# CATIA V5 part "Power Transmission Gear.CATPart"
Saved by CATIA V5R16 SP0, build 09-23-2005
Part number: Housing
Bounding box of the stored display mesh (mm): x -51 to 51, y 0 to 88, z 0 to 134.987
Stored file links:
  C:\V5_education\CATIA Data\ASD\Power Transmission Gear Assembly\Assembly Data\Power Transmission Gear.CATPart
  C:\V5_education\CATIA Data\ASD\Power Transmission Gear Assembly\Power Transmission Gear Assembly.CATProduct
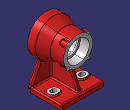
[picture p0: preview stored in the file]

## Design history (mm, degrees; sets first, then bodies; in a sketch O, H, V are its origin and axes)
Set1 "Reference Data"
  Point1 "Center Point": (0, 0, 0)
  Point2 "Hard Point": (0, 0, 91), relative to Point1
  Set2 "Datum Body"
    Plane1: type Offset, RefPlane zx-plane, Offset 88
    Plane2: type Offset, RefPlane zx-plane, Offset 76
    Plane3: type Offset, RefPlane zx-plane, Offset 6
    Plane4: type Offset, RefPlane xy-plane, Offset 4
    Plane5: type Offset, RefPlane yz-plane, Offset 51 {= -Plane6.Offset}
    Plane6: type Offset, RefPlane yz-plane, Offset -51
  Extrude1: Element1 Sketch1, Lim1 201, Lim2 115, Direction zx-plane
  Sketch1 on zx-plane, origin (0, 0, 0), H (-1, 0, 0), V (0, 0, 1)
    point P1 (0, 167.3167)
    line L1 (0, 167.3167) -> (0, 91)
    line L2 (0, 91) -> (-87.8725, 91)
    distance H L2 = 91
    coincidence: P1 V
    vertical: L1 V
    horizontal: L2 H
Body1 (main body)
  Body2 "Revolution Body"
    Sketch2 on yz-plane, origin (0, 0, 0), H (0, 1, 0), V (0, 0, 1)
      reference projected point E1 (0, 91) from Point2
      point P1 (0, 91)
      line L1 (0, 91) -> (0, 135)
      line L2 (0, 135) -> (18, 135)
      point P3 (18, 135)
      line L3 (18, 135) -> (44, 125.5)
      point P4 (44, 125.5)
      line L4 (44, 125.5) -> (76, 125.5)
      line L5 (76, 125.5) -> (76, 91)
      axis line L6 (0, 91) -> (76, 91)
      reference intersected line E2 through (76, 0) direction (0, 1) from Plane2
      distance L1 P4 = 44
      distance L1 P3 = 18
      distance L2 L6 = 44
      distance L6 L4 = 34.5
      vertical: L1 V, L5 V
      horizontal: L2 H, L6 H
      coincidence: L1 E1, P1 E1, L5 E2
    Shaft1: profile Sketch2, axis Sketch2.L6, angle 360
    Fillet1: radius 3, on edge [face of Shaft1 from Sketch2.L2 | face of Shaft1 from Sketch2.L3]; edge [face of Shaft1 from Sketch2.L3 | face of Shaft1 from Sketch2.L4]
    Body3
      Sketch3 on Plane2, origin (0, 76, 91), H (-1, 0, 0), V (0, 0, 1)
        construction circle A1 centre (0, 0) radius 32
        circle A2 centre (22.6274, 22.6274) radius 6
        point P1 (22.6274, 22.6274)
        construction line L1 (22.6274, 22.6274) -> (0, 0)
        radius A1 = 32
        angle H L1 = 45
        radius A2 = 6
        coincidence: P1 A1
      Pad1: profile Sketch3, direction (0, -1, 0), length 16
      Fillet2: radius 3, on end face of Pad1
      CircPattern1: of the body so far, instances 4, angular step 90 {= 360.0*1 deg/CircPattern1.AngularNumber}, axis from face of Shaft1 from Sketch2.L4
    Assemble1: tool Body3
    Fillet3: radius 3, on edge [face of Shaft1 from Sketch2.L4 | face of CircPattern1] (x3); edge [face of Pad1 from Sketch3.A2 | face of Shaft1 from Sketch2.L4]
  Assemble2: tool Body2
  Body4 "Base Body"
    Sketch4 on xy-plane, origin (0, 0, 0), H (0, 1, 0), V (-1, 0, 0)
      line L1 (6, 51) -> (88, 51)
      line L2 (88, 51) -> (88, -51)
      line L3 (88, -51) -> (6, -51)
      line L4 (6, -51) -> (6, 51)
      reference intersected line E1 through (88, 0) direction (0, 1) from Plane1
      reference intersected line E2 through (6, 0) direction (0, 1) from Plane3
      reference intersected line E3 through (0, 51) direction (1, 0) from Plane6
      horizontal: L1 H, L3 H
      vertical: L2 V, L4 V
      symmetry: L1 L3 H
      coincidence: L2 E1, L4 E2, L1 E3
    Pad2: profile Sketch4, direction (0, 0, 1), length 11
    Fillet4: radius 3, on edge [face of Pad2 from Sketch4.L2 | face of Pad2 from Sketch4.L3]; edge [face of Pad2 from Sketch4.L1 | face of Pad2 from Sketch4.L2]
    Fillet5: radius 3, on edge [face of Pad2 from Sketch4.L3 | end face of Pad2]
    Body5 "Ellongate Hole Body"
      Sketch5 on xy-plane, origin (0, 0, 0), H (0, 1, 0), V (-1, 0, 0)
        construction line L1 (51, -32) -> (51, -36)
        point P1 (51, -32)
        point P2 (51, -36)
        line L2 (61, -32) -> (61, -36)
        line L3 (41, -36) -> (41, -32)
        arc A1 centre (51, -36) radius 10 from (61, -36) to (41, -36) cw
        arc A2 centre (51, -32) radius 10 from (41, -32) to (61, -32) cw
        construction line L4 (51, -34) -> (41, -34)
        point P7 (51, -34)
        point P8 (41, -34)
        reference intersected line E1 through (88, 0) direction (0, 1) from Plane1
        reference intersected line E2 through (0, 0) direction (1, 0) from yz-plane
        distance L1 L2 = 10
        distance P1 P2 = 4
        distance E1 L1 = 37
        distance E2 P1 = 32
        vertical: L1 V
        tangency: A1 L2, A2 L2, A1 L3, A2 L3
        midpoint: P7 L1, P8 L3
        horizontal: L4 H
      Pad3: profile Sketch5, direction (0, 0, 1), length 14
      Mirror1: of the body so far, about yz-plane
    Assemble3: tool Body5
    Fillet6: radius 3, on edge [face of Pad3 from Sketch5.L2 | end face of Pad2]; edge [face of Mirror1 | end face of Pad2]
    Body6
      Sketch6 on zx-plane, origin (0, 0, 0), H (-1, 0, 0), V (0, 0, 1)
        line L1 (0, 0) -> (51, 0)
        point P1 (51, 0)
        line L2 (51, 0) -> (51, 11)
        point P2 (51, 11)
        line L3 (51, 11) -> (13.6954, 91)
        point P3 (13.6954, 91)
        line L4 (13.6954, 91) -> (0, 91)
        point P4 (0, 91)
        construction line L5 (0, 91) -> (0, 0)
        reference intersected line E1 through (51, 0) direction (0, -1) from Plane6
        reference projected point E2 (0, 91) from Point2
        point P5 (0, 91)
        point P6 (-13.6954, 91)
        point P7 (-51, 11)
        point P8 (-51, 0)
        point P9 (0, 0)
        line L6 (-13.6954, 91) -> (0, 91)
        line L7 (-51, 11) -> (-13.6954, 91)
        line L8 (-51, 0) -> (-51, 11)
        line L9 (0, 0) -> (-51, 0)
        angle L3 L1 = 65
        distance H P2 = 11
        horizontal: L1 H, L4 H
        vertical: L2 V, L5 V
        coincidence: P4 V, L2 E1, L4 E2, O P9, P4 P5
        symmetry: P4 P5 V, P3 P6 V, P2 P7 V, P1 P8 V, O P9 V, L4 L6 V, L3 L7 V, L2 L8 V, L1 L9 V
      Pad4: profile Sketch6, direction (0, 1, 0), length 16, opposite side length -6
      Fillet7: radius 20, on edge [face of Pad4 from Sketch6.L8 | face of Pad4 from Sketch6.L7]; edge [face of Pad4 from Sketch6.L3 | face of Pad4 from Sketch6.L2]
      Fillet8: radius 3, on edge [face of Pad4 from Sketch6.L7 | end face of Pad4]; edge [face of Pad4 from Sketch6.L3 | end face of Pad4]
    Assemble4: tool Body6
    Fillet9: radius 3, on edge [end face of Pad2 | end face of Pad4]
    Body7
      Sketch7 on yz-plane, origin (0, 0, 0), H (0, 1, 0), V (0, 0, 1)
        point P1 (6, 0)
        line L1 (6, 0) -> (6, 91)
        line L2 (6, 91) -> (46.042, 91)
        line L3 (46.042, 91) -> (84.6692, 0)
        point P4 (84.6692, 0)
        line L4 (84.6692, 0) -> (6, 0)
        reference intersected line E1 (6, 11) -> (88, 11) from end face of Pad2
        point P7 (80, 11)
        reference intersected line E2 through (88, 0) direction (0, 1) from Plane1
        reference intersected line E3 through (6, 0) direction (0, 1) from Plane3
        reference projected point E4 (0, 91) from Point2
        distance P7 E2 = 8
        angle L3 E1 = 67
        coincidence: P1 H, P4 H, L3 P7, E1 P7, L1 E3, L2 E4
        vertical: L1 V
        horizontal: L2 H, L4 H
      Pad5: profile Sketch7, direction (1, 0, 0), length 5, mirrored extent
      Fillet10: radius 3, on edge [face of Pad5 from Sketch7.L3 | end face of Pad5]; edge [start face of Pad5 | face of Pad5 from Sketch7.L3]
    Assemble5: tool Body7
    Fillet11: radius 3, on edge [end face of Pad4 | end face of Pad5]
    Body8
      Sketch8 on yz-plane, origin (0, 0, 0), H (0, 1, 0), V (0, 0, 1)
        point P1 (6, 0)
        line L1 (6, 0) -> (12, 0)
        line L2 (12, 0) -> (12, 4)
        line L3 (12, 4) -> (6, 4)
        line L4 (6, 4) -> (6, 0)
        reference intersected line E1 through (6, 0) direction (0, 1) from Plane3
        reference intersected line E2 through (0, 4) direction (-1, 0) from Plane4
        reference intersected line E3 through (6, 0) direction (0, 1) from Plane3
        distance L2 E3 = 6
        coincidence: P1 H, L4 E1, L3 E2
        horizontal: L1 H, L3 H
        vertical: L2 V, L4 V
      Pad6: profile Sketch8, direction (1, 0, 0), up to Plane5, opposite side up to Plane6
      Fillet12: radius 3, on edge [face of Pad6 from Sketch8.L3 | face of Pad6 from Sketch8.L2]
    Remove1: tool Body8
    Fillet13: radius 3, on edge [face of Pad6 from Sketch8.L3 | start face of Pad4]
    Fillet14: radius 3, on edge [face of Pad4 | face of Pad4 from Sketch6.L3]; edge [face of Pad4 | face of Pad4 from Sketch6.L7]
  Assemble6: tool Body4
  Fillet15: radius 3, on edge [face of Shaft1 from Sketch2.L3 | end face of Pad5]
  Body9 "Hole Body"
    Sketch9 on yz-plane, origin (0, 0, 0), H (0, 1, 0), V (0, 0, 1)
      axis line L1 (0, 91) -> (81.5372, 91)
      line L2 (0, 91) -> (0, 122)
      line L3 (0, 122) -> (21, 122)
      line L4 (21, 122) -> (21, 117)
      line L5 (21, 117) -> (51, 117)
      line L6 (51, 117) -> (51, 112)
      line L7 (51, 112) -> (55, 112)
      line L8 (55, 112) -> (55, 117)
      point P8 (55, 117)
      line L9 (55, 117) -> (76, 117)
      line L10 (76, 117) -> (76, 91)
      point P10 (76, 91)
      distance L2 L4 = 21
      distance L4 L6 = 30
      distance L10 L8 = 21
      distance L10 L2 = 76
      distance L1 L9 = 26
      distance L7 L1 = 21
      distance L3 L1 = 31
      horizontal: L1 H, L3 H, L5 H, L7 H, L9 H
      vertical: L2 V, L4 V, L6 V, L8 V, L10 V
      coincidence: P8 L5, P10 L1
    Shaft2: profile Sketch9, axis Sketch9.L1, angle 360
    Fillet16: radius 3, on edge [face of Shaft2 from Sketch9.L5 | face of Shaft2 from Sketch9.L6]
    Fillet17: radius 0.3, on edge [face of Shaft2 from Sketch9.L3 | face of Shaft2 from Sketch9.L4]; edge [face of Shaft2 from Sketch9.L8 | face of Shaft2 from Sketch9.L9]
    Body10 "Ellongate Hole Body"
      Sketch10 on xy-plane, origin (0, 0, 0), H (0, 1, 0), V (-1, 0, 0)
        construction line L1 (51, -32) -> (51, -36)
        point P1 (51, -32)
        point P2 (51, -36)
        line L2 (56, -32) -> (56, -36)
        line L3 (46, -36) -> (46, -32)
        arc A1 centre (51, -36) radius 5 from (56, -36) to (46, -36) cw
        arc A2 centre (51, -32) radius 5 from (46, -32) to (56, -32) cw
        construction line L4 (51, -34) -> (46, -34)
        point P7 (51, -34)
        point P8 (46, -34)
        reference intersected line E1 through (88, 0) direction (0, 1) from Plane1
        reference intersected line E2 through (0, 0) direction (1, 0) from yz-plane
        distance L1 L2 = 5
        distance P1 P2 = 4
        distance E1 L1 = 37
        distance E2 P1 = 32
        vertical: L1 V
        tangency: A1 L2, A2 L2, A1 L3, A2 L3
        midpoint: P7 L1, P8 L3
        horizontal: L4 H
      Pad7: profile Sketch10, direction (0, 0, 1), length 14
      Mirror2: of the body so far, about yz-plane
    Assemble7: tool Body10
  Remove2: tool Body9
  Body11 "M4mm Tab Hole Body"
    Body12
      Sketch11 "M4 Tab Hole Diameter" on zx-plane, origin (0, 0, 91), H (1, 0, 0), V (0, 0, 1)
        construction circle A1 centre (0, 0) radius 37
        point P1 (26.163, 26.163)
        construction line L1 (26.163, 26.163) -> (0, 0)
        radius A1 = 37
        angle H L1 = 45
        coincidence: P1 A1
      Sketch12 on zx-plane, origin (-22.6274, 0, 113.6274), H (1, 0, 0), V (0, 0, -1)
        point P1 (48.7904, -3.5355)
        reference projected point E1 (48.7904, -3.5355) from Sketch11.P1
        coincidence: E1 P1
      Hole1: placed by Sketch12, at (26.163, 0, 117.163) direction (0, 1, 0), diameter 3.242, depth 12, V-bottom angle 120, threaded "M4", thread diameter 4, thread depth 8, pitch 0.7
      CircPattern2: of the body so far, instances 4, angular step 90 {= 360.0*1 deg/CircPattern2.AngularNumber}, axis from face of Shaft1 from Sketch2.L4
    Assemble8: tool Body12
    Body13
      Sketch13 "M4 Tab Hole Diameter" on Plane2, origin (0, 76, 91), H (-1, 0, 0), V (0, 0, 1)
        construction circle A1 centre (0, 0) radius 32
        point P1 (22.6274, 22.6274)
        construction line L1 (22.6274, 22.6274) -> (0, 0)
        radius A1 = 32
        angle H L1 = 45
        coincidence: P1 A1
      Sketch14 on Plane2, origin (-22.6274, 76, 113.6274), H (1, 0, 0), V (0, 0, -1)
        point P1 (0, 0)
        reference projected point E1 (0, 0) from Sketch13.P1
        coincidence: E1 P1
      Hole2: placed by Sketch14, at (-22.6274, 76, 113.6274) direction (0, -1, 0), diameter 3.242, depth 12, V-bottom angle 120, threaded "M4", thread diameter 4, thread depth 8, pitch 0.7
      CircPattern3: of the body so far, instances 4, angular step 90 {= 360.0*1 deg/CircPattern3.AngularNumber}, axis from face of Shaft1 from Sketch2.L4
    Assemble9: tool Body13
  Assemble10: tool Body11
  AssyPrtSPLIT1: _MechModInactiveResultOUT result of AssyPrtSPLIT1, SplitPlane Extrude1, deactivated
